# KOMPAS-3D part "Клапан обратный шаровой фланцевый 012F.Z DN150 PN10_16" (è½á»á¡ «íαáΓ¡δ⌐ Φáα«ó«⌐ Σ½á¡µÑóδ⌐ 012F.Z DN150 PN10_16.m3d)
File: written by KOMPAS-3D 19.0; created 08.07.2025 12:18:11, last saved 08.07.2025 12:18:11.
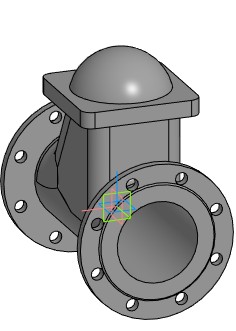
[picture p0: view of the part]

Document properties: Полное имя файла: E:\Dendor Работа Сачек\3D для проектировщиков\5.3 Тип 012F, 012F.Z Клапан обратный шаровой фланцевый\stp_Клапан обратный шаровой фланцевый 012F.Z PN10_16\Клапан обратный шаровой фланцевый 012F.Z DN150 PN10_16.m3d

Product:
- Part/product: Клапан обратный шаровой фланцевый 012F.Z DN150 PN10_16

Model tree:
1. Операция без истории:1  (labels: Клапан обратный шаровой фланцевый 012F.Z DN150 PN10_16)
